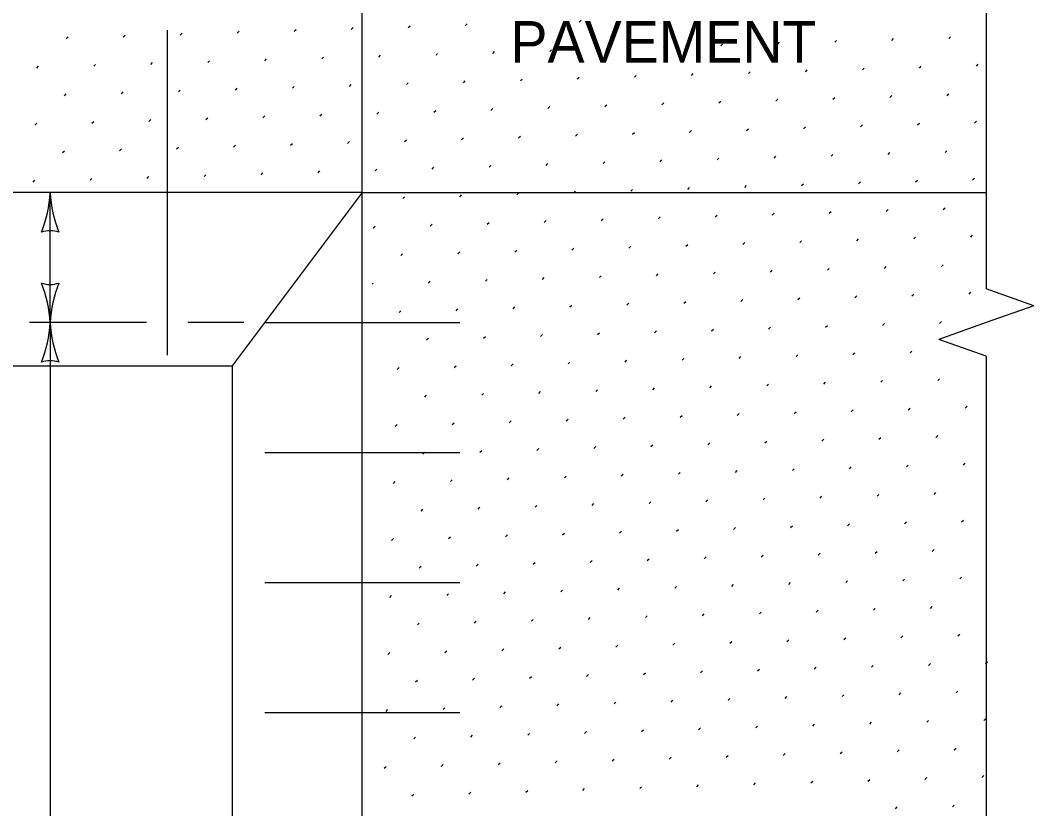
# Model space of a CAD drawing. Extents: x 49991.4 to 50021, y 49987.6 to 50011.4.
# Drawn here: x 50005.45 to 50007.398, y 49990.619 to 49992.135 of the extents above; entities that cross this region are included whole.
import ezdxf

# ---------------------------------------------------------------- set-up
doc = ezdxf.new("R2010")
doc.units = 0
for name, color, linetype in [('Level 1', 7, 'Continuous'), ('Level 10', 7, 'Continuous'), ('Level 2', 7, 'Continuous'), ('Level 3', 7, 'Continuous'), ('Level 4', 7, 'Continuous'), ('Level 6', 7, 'Continuous')]:
    doc.layers.add(name, color=color, linetype=linetype)

msp = doc.modelspace()

# ---------------------------------------------------------------- linework, layer by layer
at = {"layer": 'Level 1'}
for p, q in [((50006.1071, 49991.8039), (50006.1071, 49992.8039)), ((50006.1071, 49991.8039), (50002.3571, 49991.8039)), ((50006.1071, 49991.8039), (50005.8571, 49991.4706)), ((50006.1071, 49988.8039), (50006.1071, 49991.8039)), ((50006.1071, 49991.8039), (50007.3071, 49991.8039)), ((50002.6071, 49991.4706), (50005.8571, 49991.4706)), ((50005.8571, 49991.4706), (50005.8571, 49989.1372))]:
    msp.add_line(p, q, dxfattribs=at)
at = {"layer": 'Level 10'}
for p, q in [((50006.3052, 49992.1249), (50006.3087, 49992.1284)), ((50006.4148, 49992.1284), (50006.4183, 49992.1319)), ((50006.5244, 49992.1319), (50006.5279, 49992.1355)), ((50005.7571, 49992.1071), (50005.7607, 49992.1107)), ((50005.8668, 49992.1107), (50005.8703, 49992.1142)), ((50005.9764, 49992.1142), (50005.9799, 49992.1178)), ((50006.086, 49992.1178), (50006.0895, 49992.1213)), ((50006.1956, 49992.1213), (50006.1991, 49992.1248)), ((50005.5379, 49992.1001), (50005.5415, 49992.1036)), ((50005.6475, 49992.1036), (50005.6511, 49992.1071)), ((50006.7967, 49992.086), (50006.8002, 49992.0895)), ((50006.9063, 49992.0895), (50006.9098, 49992.0931)), ((50007.0159, 49992.0931), (50007.0194, 49992.0966)), ((50007.1255, 49992.0966), (50007.129, 49992.1002)), ((50007.2351, 49992.1002), (50007.2386, 49992.1037)), ((50006.139, 49992.0647), (50006.1425, 49992.0683)), ((50006.2486, 49992.0683), (50006.2521, 49992.0718)), ((50006.3582, 49992.0718), (50006.3618, 49992.0754)), ((50006.4678, 49992.0754), (50006.4714, 49992.0789)), ((50006.5774, 49992.0789), (50006.581, 49992.0824)), ((50006.687, 49992.0824), (50006.6906, 49992.086)), ((50005.591, 49992.047), (50005.5945, 49992.0506)), ((50005.7006, 49992.0506), (50005.7041, 49992.0541)), ((50005.8102, 49992.0541), (50005.8137, 49992.0576)), ((50005.9198, 49992.0576), (50005.9233, 49992.0612)), ((50006.0294, 49992.0612), (50006.0329, 49992.0647)), ((50007.2881, 49992.0471), (50007.2917, 49992.0507)), ((50005.4814, 49992.0435), (50005.4849, 49992.047)), ((50006.6305, 49992.0259), (50006.634, 49992.0294)), ((50006.7401, 49992.0294), (50006.7436, 49992.033)), ((50006.8497, 49992.033), (50006.8532, 49992.0365)), ((50006.9593, 49992.0365), (50006.9628, 49992.04)), ((50007.0689, 49992.04), (50007.0724, 49992.0436)), ((50007.1785, 49992.0436), (50007.182, 49992.0471)), ((50006.0824, 49992.0082), (50006.086, 49992.0117)), ((50006.192, 49992.0117), (50006.1956, 49992.0152)), ((50006.3016, 49992.0152), (50006.3052, 49992.0188)), ((50006.4113, 49992.0188), (50006.4148, 49992.0223)), ((50006.5209, 49992.0223), (50006.5244, 49992.0259)), ((50005.5344, 49991.9904), (50005.5379, 49991.994)), ((50005.644, 49991.994), (50005.6475, 49991.9975)), ((50005.7536, 49991.9975), (50005.7571, 49992.0011)), ((50005.8632, 49992.0011), (50005.8667, 49992.0046)), ((50005.9728, 49992.0046), (50005.9764, 49992.0082)), ((50007.1219, 49991.987), (50007.1255, 49991.9905)), ((50007.2315, 49991.9906), (50007.2351, 49991.9941)), ((50006.5739, 49991.9693), (50006.5774, 49991.9728)), ((50006.6835, 49991.9728), (50006.687, 49991.9764)), ((50006.7931, 49991.9764), (50006.7966, 49991.9799)), ((50006.9027, 49991.9799), (50006.9063, 49991.9835)), ((50007.0123, 49991.9835), (50007.0159, 49991.987)), ((50005.9162, 49991.948), (50005.9198, 49991.9516)), ((50006.0259, 49991.9516), (50006.0294, 49991.9551)), ((50006.1355, 49991.9551), (50006.139, 49991.9587)), ((50006.2451, 49991.9587), (50006.2486, 49991.9622)), ((50006.3547, 49991.9622), (50006.3582, 49991.9657)), ((50006.4643, 49991.9658), (50006.4678, 49991.9693)), ((50005.4778, 49991.9339), (50005.4813, 49991.9374)), ((50005.5874, 49991.9374), (50005.591, 49991.9409)), ((50005.697, 49991.941), (50005.7006, 49991.9445)), ((50005.8066, 49991.9445), (50005.8102, 49991.948)), ((50007.0654, 49991.9304), (50007.0689, 49991.934)), ((50007.175, 49991.934), (50007.1785, 49991.9375)), ((50007.2846, 49991.9375), (50007.2881, 49991.9411)), ((50006.4077, 49991.9092), (50006.4112, 49991.9127)), ((50006.5173, 49991.9127), (50006.5209, 49991.9163)), ((50006.6269, 49991.9163), (50006.6305, 49991.9198)), ((50006.7365, 49991.9198), (50006.7401, 49991.9233)), ((50006.8461, 49991.9233), (50006.8497, 49991.9269)), ((50006.9558, 49991.9269), (50006.9593, 49991.9304)), ((50005.8597, 49991.8915), (50005.8632, 49991.895)), ((50005.9693, 49991.895), (50005.9728, 49991.8985)), ((50006.0789, 49991.8986), (50006.0824, 49991.9021)), ((50006.1885, 49991.9021), (50006.192, 49991.9056)), ((50006.2981, 49991.9056), (50006.3016, 49991.9092)), ((50005.5308, 49991.8808), (50005.5344, 49991.8844)), ((50005.6405, 49991.8844), (50005.644, 49991.8879)), ((50005.7501, 49991.8879), (50005.7536, 49991.8915)), ((50006.8992, 49991.8703), (50006.9027, 49991.8739)), ((50007.0088, 49991.8739), (50007.0123, 49991.8774)), ((50007.1184, 49991.8774), (50007.1219, 49991.8809)), ((50007.228, 49991.8809), (50007.2315, 49991.8845)), ((50006.3511, 49991.8526), (50006.3547, 49991.8561)), ((50006.4607, 49991.8561), (50006.4643, 49991.8597)), ((50006.5704, 49991.8597), (50006.5739, 49991.8632)), ((50006.68, 49991.8632), (50006.6835, 49991.8668)), ((50006.7896, 49991.8668), (50006.7931, 49991.8703)), ((50005.6935, 49991.8313), (50005.697, 49991.8349)), ((50005.8031, 49991.8349), (50005.8066, 49991.8384)), ((50005.9127, 49991.8384), (50005.9162, 49991.842)), ((50006.0223, 49991.842), (50006.0258, 49991.8455)), ((50006.1319, 49991.8455), (50006.1355, 49991.8491)), ((50006.2415, 49991.8491), (50006.2451, 49991.8526)), ((50005.4743, 49991.8243), (50005.4778, 49991.8278)), ((50005.5839, 49991.8278), (50005.5874, 49991.8313)), ((50006.8426, 49991.8137), (50006.8461, 49991.8173)), ((50006.9522, 49991.8173), (50006.9557, 49991.8208)), ((50007.0618, 49991.8208), (50007.0654, 49991.8244)), ((50007.1714, 49991.8244), (50007.175, 49991.8279)), ((50007.281, 49991.8279), (50007.2846, 49991.8314)), ((50005.5071, 49991.5539), (50005.5071, 49991.8039)), ((50006.185, 49991.7925), (50006.1885, 49991.796)), ((50006.2946, 49991.796), (50006.2981, 49991.7996)), ((50006.4042, 49991.7996), (50006.4077, 49991.8031)), ((50006.5138, 49991.8031), (50006.5173, 49991.8066)), ((50006.6234, 49991.8067), (50006.6269, 49991.8102)), ((50006.733, 49991.8102), (50006.7365, 49991.8137)), ((50006.6764, 49991.7536), (50006.68, 49991.7572)), ((50006.786, 49991.7572), (50006.7896, 49991.7607)), ((50006.8956, 49991.7607), (50006.8992, 49991.7642)), ((50007.0052, 49991.7643), (50007.0088, 49991.7678)), ((50007.1149, 49991.7678), (50007.1184, 49991.7713)), ((50007.2245, 49991.7713), (50007.228, 49991.7749)), ((50006.1284, 49991.7359), (50006.1319, 49991.7394)), ((50006.238, 49991.7395), (50006.2415, 49991.743)), ((50006.3476, 49991.743), (50006.3511, 49991.7465)), ((50006.4572, 49991.7465), (50006.4607, 49991.7501)), ((50006.5668, 49991.7501), (50006.5703, 49991.7536)), ((50007.1679, 49991.7148), (50007.1714, 49991.7183)), ((50007.2775, 49991.7183), (50007.281, 49991.7218)), ((50006.6198, 49991.697), (50006.6234, 49991.7006)), ((50006.7295, 49991.7006), (50006.733, 49991.7041)), ((50006.8391, 49991.7041), (50006.8426, 49991.7077)), ((50006.9487, 49991.7077), (50006.9522, 49991.7112)), ((50007.0583, 49991.7112), (50007.0618, 49991.7148)), ((50006.1814, 49991.6829), (50006.1849, 49991.6864)), ((50006.291, 49991.6864), (50006.2946, 49991.69)), ((50006.4006, 49991.69), (50006.4042, 49991.6935)), ((50006.5102, 49991.6935), (50006.5138, 49991.697)), ((50007.1113, 49991.6582), (50007.1148, 49991.6617)), ((50007.2209, 49991.6617), (50007.2245, 49991.6653)), ((50006.4537, 49991.6369), (50006.4572, 49991.6405)), ((50006.5633, 49991.6405), (50006.5668, 49991.644)), ((50006.6729, 49991.644), (50006.6764, 49991.6475)), ((50006.7825, 49991.6476), (50006.786, 49991.6511)), ((50006.8921, 49991.6511), (50006.8956, 49991.6546)), ((50007.0017, 49991.6546), (50007.0052, 49991.6582)), ((50006.1261, 49991.6275), (50006.1284, 49991.6298)), ((50006.2344, 49991.6298), (50006.238, 49991.6334)), ((50006.3441, 49991.6334), (50006.3476, 49991.6369)), ((50006.9451, 49991.5981), (50006.9487, 49991.6016)), ((50007.0547, 49991.6016), (50007.0583, 49991.6051)), ((50007.1643, 49991.6052), (50007.1679, 49991.6087)), ((50007.274, 49991.6087), (50007.2775, 49991.6122)), ((50006.3971, 49991.5804), (50006.4006, 49991.5839)), ((50006.5067, 49991.5839), (50006.5102, 49991.5874)), ((50006.6163, 49991.5874), (50006.6198, 49991.591)), ((50006.7259, 49991.591), (50006.7294, 49991.5945)), ((50006.8355, 49991.5945), (50006.8391, 49991.5981)), ((50006.1779, 49991.5733), (50006.1814, 49991.5768)), ((50006.2875, 49991.5768), (50006.291, 49991.5803)), ((50006.8886, 49991.5415), (50006.8921, 49991.545)), ((50006.9982, 49991.545), (50007.0017, 49991.5486)), ((50007.1078, 49991.5486), (50007.1113, 49991.5521)), ((50007.2174, 49991.5521), (50007.2209, 49991.5557)), ((50006.2309, 49991.5202), (50006.2344, 49991.5238)), ((50006.3405, 49991.5238), (50006.344, 49991.5273)), ((50006.4501, 49991.5273), (50006.4537, 49991.5309)), ((50006.5597, 49991.5309), (50006.5633, 49991.5344)), ((50006.6693, 49991.5344), (50006.6729, 49991.5379)), ((50006.7789, 49991.5379), (50006.7825, 49991.5415)), ((50006.7224, 49991.4814), (50006.7259, 49991.4849)), ((50006.832, 49991.4849), (50006.8355, 49991.4885)), ((50006.9416, 49991.4885), (50006.9451, 49991.492)), ((50007.0512, 49991.492), (50007.0547, 49991.4955)), ((50007.1608, 49991.4955), (50007.1643, 49991.4991)), ((50006.1743, 49991.4637), (50006.1779, 49991.4672)), ((50006.2839, 49991.4672), (50006.2875, 49991.4707)), ((50006.3935, 49991.4707), (50006.3971, 49991.4743)), ((50006.5031, 49991.4743), (50006.5067, 49991.4778)), ((50006.6128, 49991.4778), (50006.6163, 49991.4814)), ((50007.2138, 49991.4425), (50007.2174, 49991.446)), ((50006.6658, 49991.4248), (50006.6693, 49991.4283)), ((50006.7754, 49991.4283), (50006.7789, 49991.4319)), ((50006.885, 49991.4319), (50006.8885, 49991.4354)), ((50006.9946, 49991.4354), (50006.9982, 49991.439)), ((50007.1042, 49991.439), (50007.1078, 49991.4425)), ((50006.2274, 49991.4106), (50006.2309, 49991.4142)), ((50006.337, 49991.4142), (50006.3405, 49991.4177)), ((50006.4466, 49991.4177), (50006.4501, 49991.4212)), ((50006.5562, 49991.4213), (50006.5597, 49991.4248)), ((50007.1573, 49991.3859), (50007.1608, 49991.3895)), ((50007.2669, 49991.3895), (50007.2704, 49991.393)), ((50006.4996, 49991.3647), (50006.5031, 49991.3682)), ((50006.6092, 49991.3682), (50006.6128, 49991.3718)), ((50006.7188, 49991.3718), (50006.7224, 49991.3753)), ((50006.8284, 49991.3753), (50006.832, 49991.3788)), ((50006.938, 49991.3788), (50006.9416, 49991.3824)), ((50007.0477, 49991.3824), (50007.0512, 49991.3859)), ((50006.1708, 49991.3541), (50006.1743, 49991.3576)), ((50006.2804, 49991.3576), (50006.2839, 49991.3611)), ((50006.39, 49991.3611), (50006.3935, 49991.3647)), ((50006.9911, 49991.3258), (50006.9946, 49991.3294)), ((50007.1007, 49991.3294), (50007.1042, 49991.3329)), ((50007.2103, 49991.3329), (50007.2138, 49991.3364)), ((50006.443, 49991.3081), (50006.4466, 49991.3116)), ((50006.5526, 49991.3116), (50006.5562, 49991.3152)), ((50006.6622, 49991.3152), (50006.6658, 49991.3187)), ((50006.7719, 49991.3187), (50006.7754, 49991.3223)), ((50006.8815, 49991.3223), (50006.885, 49991.3258)), ((50006.2238, 49991.301), (50006.2273, 49991.3046)), ((50006.3334, 49991.3046), (50006.337, 49991.3081)), ((50006.8249, 49991.2657), (50006.8284, 49991.2692)), ((50006.9345, 49991.2692), (50006.938, 49991.2728)), ((50007.0441, 49991.2728), (50007.0476, 49991.2763)), ((50007.1537, 49991.2763), (50007.1573, 49991.2799)), ((50007.2633, 49991.2799), (50007.2669, 49991.2834)), ((50006.2768, 49991.248), (50006.2804, 49991.2515)), ((50006.3865, 49991.2515), (50006.39, 49991.2551)), ((50006.4961, 49991.2551), (50006.4996, 49991.2586)), ((50006.6057, 49991.2586), (50006.6092, 49991.2621)), ((50006.7153, 49991.2622), (50006.7188, 49991.2657)), ((50006.1672, 49991.2444), (50006.1708, 49991.248)), ((50006.7683, 49991.2091), (50006.7719, 49991.2127)), ((50006.8779, 49991.2127), (50006.8815, 49991.2162)), ((50006.9875, 49991.2162), (50006.9911, 49991.2197)), ((50007.0971, 49991.2197), (50007.1007, 49991.2233)), ((50007.2067, 49991.2233), (50007.2103, 49991.2268)), ((50006.2203, 49991.1914), (50006.2238, 49991.1949)), ((50006.3299, 49991.195), (50006.3334, 49991.1985)), ((50006.4395, 49991.1985), (50006.443, 49991.202)), ((50006.5491, 49991.202), (50006.5526, 49991.2056)), ((50006.6587, 49991.2056), (50006.6622, 49991.2091)), ((50007.2598, 49991.1703), (50007.2633, 49991.1738)), ((50006.6021, 49991.149), (50006.6057, 49991.1525)), ((50006.7117, 49991.1525), (50006.7153, 49991.1561)), ((50006.8213, 49991.1561), (50006.8249, 49991.1596)), ((50006.931, 49991.1596), (50006.9345, 49991.1632)), ((50007.0406, 49991.1632), (50007.0441, 49991.1667)), ((50007.1502, 49991.1667), (50007.1537, 49991.1703)), ((50006.1637, 49991.1348), (50006.1672, 49991.1384)), ((50006.2733, 49991.1384), (50006.2768, 49991.1419)), ((50006.3829, 49991.1419), (50006.3864, 49991.1455)), ((50006.4925, 49991.1455), (50006.4961, 49991.149)), ((50007.0936, 49991.1101), (50007.0971, 49991.1137)), ((50007.2032, 49991.1137), (50007.2067, 49991.1172)), ((50006.5456, 49991.0924), (50006.5491, 49991.096)), ((50006.6552, 49991.096), (50006.6587, 49991.0995)), ((50006.7648, 49991.0995), (50006.7683, 49991.103)), ((50006.8744, 49991.1031), (50006.8779, 49991.1066)), ((50006.984, 49991.1066), (50006.9875, 49991.1101)), ((50006.2167, 49991.0818), (50006.2203, 49991.0853)), ((50006.3263, 49991.0853), (50006.3299, 49991.0889)), ((50006.4359, 49991.0889), (50006.4395, 49991.0924)), ((50007.037, 49991.0536), (50007.0406, 49991.0571)), ((50007.1466, 49991.0571), (50007.1502, 49991.0606)), ((50007.2562, 49991.0607), (50007.2598, 49991.0642)), ((50006.3794, 49991.0323), (50006.3829, 49991.0358)), ((50006.489, 49991.0359), (50006.4925, 49991.0394)), ((50006.5986, 49991.0394), (50006.6021, 49991.0429)), ((50006.7082, 49991.0429), (50006.7117, 49991.0465)), ((50006.8178, 49991.0465), (50006.8213, 49991.05)), ((50006.9274, 49991.05), (50006.9309, 49991.0536)), ((50006.1602, 49991.0252), (50006.1637, 49991.0288)), ((50006.2698, 49991.0288), (50006.2733, 49991.0323)), ((50006.8708, 49990.9934), (50006.8744, 49990.997)), ((50006.9804, 49990.997), (50006.984, 49991.0005)), ((50007.0901, 49991.0005), (50007.0936, 49991.0041)), ((50007.1997, 49991.0041), (50007.2032, 49991.0076)), ((50006.3228, 49990.9757), (50006.3263, 49990.9793)), ((50006.4324, 49990.9793), (50006.4359, 49990.9828)), ((50006.542, 49990.9828), (50006.5455, 49990.9864)), ((50006.6516, 49990.9864), (50006.6552, 49990.9899)), ((50006.7612, 49990.9899), (50006.7648, 49990.9934)), ((50006.2132, 49990.9722), (50006.2167, 49990.9757)), ((50006.8143, 49990.9369), (50006.8178, 49990.9404)), ((50006.9239, 49990.9404), (50006.9274, 49990.9439)), ((50007.0335, 49990.944), (50007.037, 49990.9475)), ((50007.1431, 49990.9475), (50007.1466, 49990.951)), ((50007.2527, 49990.951), (50007.2562, 49990.9546)), ((50006.1566, 49990.9156), (50006.1601, 49990.9192)), ((50006.2662, 49990.9192), (50006.2698, 49990.9227)), ((50006.3758, 49990.9227), (50006.3794, 49990.9262)), ((50006.4854, 49990.9262), (50006.489, 49990.9298)), ((50006.595, 49990.9298), (50006.5986, 49990.9333)), ((50006.7047, 49990.9333), (50006.7082, 49990.9369)), ((50007.3057, 49990.898), (50007.3093, 49990.9015)), ((50006.6481, 49990.8768), (50006.6516, 49990.8803)), ((50006.7577, 49990.8803), (50006.7612, 49990.8838)), ((50006.8673, 49990.8838), (50006.8708, 49990.8874)), ((50006.9769, 49990.8874), (50006.9804, 49990.8909)), ((50007.0865, 49990.8909), (50007.09, 49990.8945)), ((50007.1961, 49990.8945), (50007.1997, 49990.898)), ((50006.2096, 49990.8626), (50006.2132, 49990.8661)), ((50006.3193, 49990.8661), (50006.3228, 49990.8697)), ((50006.4289, 49990.8697), (50006.4324, 49990.8732)), ((50006.5385, 49990.8732), (50006.542, 49990.8767)), ((50007.1395, 49990.8379), (50007.1431, 49990.8414)), ((50007.2492, 49990.8414), (50007.2527, 49990.845)), ((50006.5915, 49990.8202), (50006.595, 49990.8237)), ((50006.7011, 49990.8237), (50006.7046, 49990.8273)), ((50006.8107, 49990.8273), (50006.8143, 49990.8308)), ((50006.9203, 49990.8308), (50006.9239, 49990.8343)), ((50007.0299, 49990.8343), (50007.0335, 49990.8379)), ((50006.1531, 49990.806), (50006.1566, 49990.8095)), ((50006.2627, 49990.8095), (50006.2662, 49990.8131)), ((50006.3723, 49990.8131), (50006.3758, 49990.8166)), ((50006.4819, 49990.8166), (50006.4854, 49990.8202)), ((50007.083, 49990.7813), (50007.0865, 49990.7849)), ((50007.1926, 49990.7849), (50007.1961, 49990.7884)), ((50007.3022, 49990.7884), (50007.3057, 49990.7919)), ((50006.4253, 49990.7601), (50006.4289, 49990.7636)), ((50006.5349, 49990.7636), (50006.5385, 49990.7671)), ((50006.6445, 49990.7671), (50006.6481, 49990.7707)), ((50006.7541, 49990.7707), (50006.7577, 49990.7742)), ((50006.8638, 49990.7742), (50006.8673, 49990.7778)), ((50006.9734, 49990.7778), (50006.9769, 49990.7813)), ((50006.2061, 49990.753), (50006.2096, 49990.7565)), ((50006.3157, 49990.7565), (50006.3192, 49990.7601)), ((50006.9168, 49990.7212), (50006.9203, 49990.7247)), ((50007.0264, 49990.7247), (50007.0299, 49990.7283)), ((50007.136, 49990.7283), (50007.1395, 49990.7318)), ((50007.2456, 49990.7318), (50007.2491, 49990.7354)), ((50006.3687, 49990.7035), (50006.3723, 49990.707)), ((50006.4784, 49990.707), (50006.4819, 49990.7106)), ((50006.588, 49990.7106), (50006.5915, 49990.7141)), ((50006.6976, 49990.7141), (50006.7011, 49990.7176)), ((50006.8072, 49990.7177), (50006.8107, 49990.7212)), ((50006.1495, 49990.6964), (50006.1531, 49990.6999)), ((50006.2591, 49990.6999), (50006.2627, 49990.7035)), ((50006.8602, 49990.6646), (50006.8637, 49990.6682)), ((50006.9698, 49990.6682), (50006.9734, 49990.6717)), ((50007.0794, 49990.6717), (50007.083, 49990.6752)), ((50007.189, 49990.6752), (50007.1926, 49990.6788)), ((50007.2986, 49990.6788), (50007.3022, 49990.6823)), ((50006.2026, 49990.6434), (50006.2061, 49990.6469)), ((50006.3122, 49990.6469), (50006.3157, 49990.6504)), ((50006.4218, 49990.6505), (50006.4253, 49990.654)), ((50006.5314, 49990.654), (50006.5349, 49990.6575)), ((50006.641, 49990.6575), (50006.6445, 49990.6611)), ((50006.7506, 49990.6611), (50006.7541, 49990.6646)), ((50007.1325, 49990.6187), (50007.136, 49990.6222)), ((50007.2421, 49990.6222), (50007.2456, 49990.6258))]:
    msp.add_line(p, q, dxfattribs=at)
at = {"layer": 'Level 3'}
for p, q in [((50005.6921, 49991.5539), (50005.4671, 49991.5539)), ((50005.5071, 49991.5539), (50005.5071, 49989.0539)), ((50005.8796, 49991.5539), (50005.7721, 49991.5539))]:
    msp.add_line(p, q, dxfattribs=at)
for centre, radius, start, end in [((50005.2849, 49991.813), 0.2223, 337.456, 357.6395), ((50005.7398, 49991.8154), 0.233, 182.8273, 202.0772), ((50005.5071, 49991.6757), 0.0548, 72.1388, 107.8612), ((50005.5071, 49991.6821), 0.0548, 252.1388, 287.8612), ((50005.2743, 49991.5424), 0.233, 2.8273, 22.0772), ((50005.7292, 49991.5447), 0.2223, 157.456, 177.6395), ((50005.2849, 49991.563), 0.2223, 337.456, 357.6395), ((50005.7398, 49991.5654), 0.233, 182.8273, 202.0772), ((50005.5071, 49991.4257), 0.0548, 72.1388, 107.8612)]:
    msp.add_arc(centre, radius, start, end, dxfattribs=at)
at = {"layer": 'Level 4'}
for p, q in [((50005.7321, 49992.1164), (50005.7321, 49991.4914)), ((50005.9196, 49991.5539), (50006.2946, 49991.5539)), ((50005.9196, 49991.3039), (50006.2946, 49991.3039)), ((50005.9196, 49991.0539), (50006.2946, 49991.0539)), ((50005.9196, 49990.8039), (50006.2946, 49990.8039))]:
    msp.add_line(p, q, dxfattribs=at)
at = {"layer": 'Level 6'}
for p, q in [((50007.3071, 49992.9039), (50007.3071, 49991.6187)), ((50007.3985, 49991.5863), (50007.3071, 49991.6187)), ((50007.3985, 49991.5863), (50007.3071, 49991.5539)), ((50007.3071, 49991.5539), (50007.2157, 49991.5215)), ((50007.3071, 49991.4891), (50007.2157, 49991.5215)), ((50007.3071, 49991.4891), (50007.3071, 49990.1187))]:
    msp.add_line(p, q, dxfattribs=at)

# ---------------------------------------------------------------- texts
at = {"layer": 'Level 2'}
msp.add_text('PAVEMENT', height=0.08, dxfattribs=at).set_placement((50006.3921, 49992.0539))

doc.saveas('drawing.dxf')
